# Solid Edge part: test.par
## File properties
Title: Thrust bearing
Author: Abhinav Rai
Template: Normal.par
Last saved by: TIET
Revision: 11
Application: Solid Edge
Accuracy: 0.99
Material: aluminum
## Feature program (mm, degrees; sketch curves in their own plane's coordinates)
sketch for "unnamed RevolvedProtrusion 1" plane through (0, 0, 0) normal (0, -1, 0) x-axis (1, 0, 0)
  line (47.625, 16.8036) -> (66.929, 16.8036)
  line (66.929, 16.8036) -> (73.025, 10.7076)
  line (73.025, 10.7076) -> (73.025, -12.0254)
  line (73.025, -12.0254) -> (66.929, -18.1214)
  line (66.929, -18.1214) -> (47.625, -18.1214)
  line (47.625, -18.1214) -> (47.625, -7.1994)
  line (61.5714, -7.1994) -> (47.625, -7.1994)
  line (61.5714, 5.8816) -> (61.5714, -7.1994)
  line (47.625, 5.8816) -> (61.5714, 5.8816)
  line (47.625, 5.8816) -> (47.625, 16.8036)
revolve "unnamed RevolvedProtrusion 1" add finite 360 deg
sketch for "unnamed RevolvedProtrusion 2" plane through (0, 0, 0) normal (1, 0, 0) x-axis (0, 1, 0)
  line (69.977, 13.7556) -> (73.0652, 13.7556)
  line (73.0652, 13.7556) -> (74.6125, 12.2083)
  line (74.6125, 12.2083) -> (74.6125, -13.4669)
  line (74.6125, -13.4669) -> (73.006, -15.0734)
  line (73.006, -15.0734) -> (69.977, -15.0734)
revolve "unnamed RevolvedProtrusion 2" add full turn 360 deg
sketch for "unnamed RevolvedProtrusion 3" plane through (0, 0, 0) normal (0, -1, 0) x-axis (1, 0, 0)
revolve "unnamed RevolvedProtrusion 3" add full turn 360 deg about sketch line (-54.9674, 10.1232) -> (-54.9674, -18.1214)
pattern "unnamed Pattern 1" of "unnamed RevolvedProtrusion 3"
pattern "unnamed Pattern 2"
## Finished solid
Body 1: solid body, 39 faces, 39 edges, 25 vertices.
  Faces by surface: torus 25, plane 6, cone 4, cylinder 4
  Edges by curve: circle 39
Bounding box of the edges (mm; curved faces can reach further): 149.225 x 149.225 x 34.925, from (-74.6125, -74.6125, -18.1214) to (74.6125, 74.6125, 16.8036).
Cylindrical faces by radius (mm): R47.625 x2, R61.5714 x1, R74.6125 x1
Conical faces (half-angle, radius in mm at the cone's reference point): 45 deg R66.929 x1, 45 deg R73.025 x1, 45 deg R73.0652 x1, 45 deg R74.6125 x1
Toroidal faces (ring radius, tube radius in mm): R-0.1023 r6.604 x25
Planar faces by outward normal: +z 3, -z 3
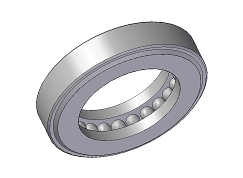
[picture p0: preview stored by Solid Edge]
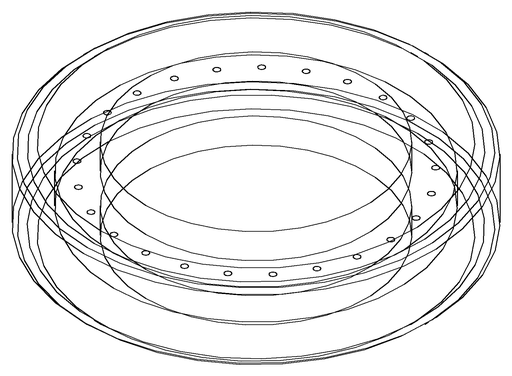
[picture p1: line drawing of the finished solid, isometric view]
